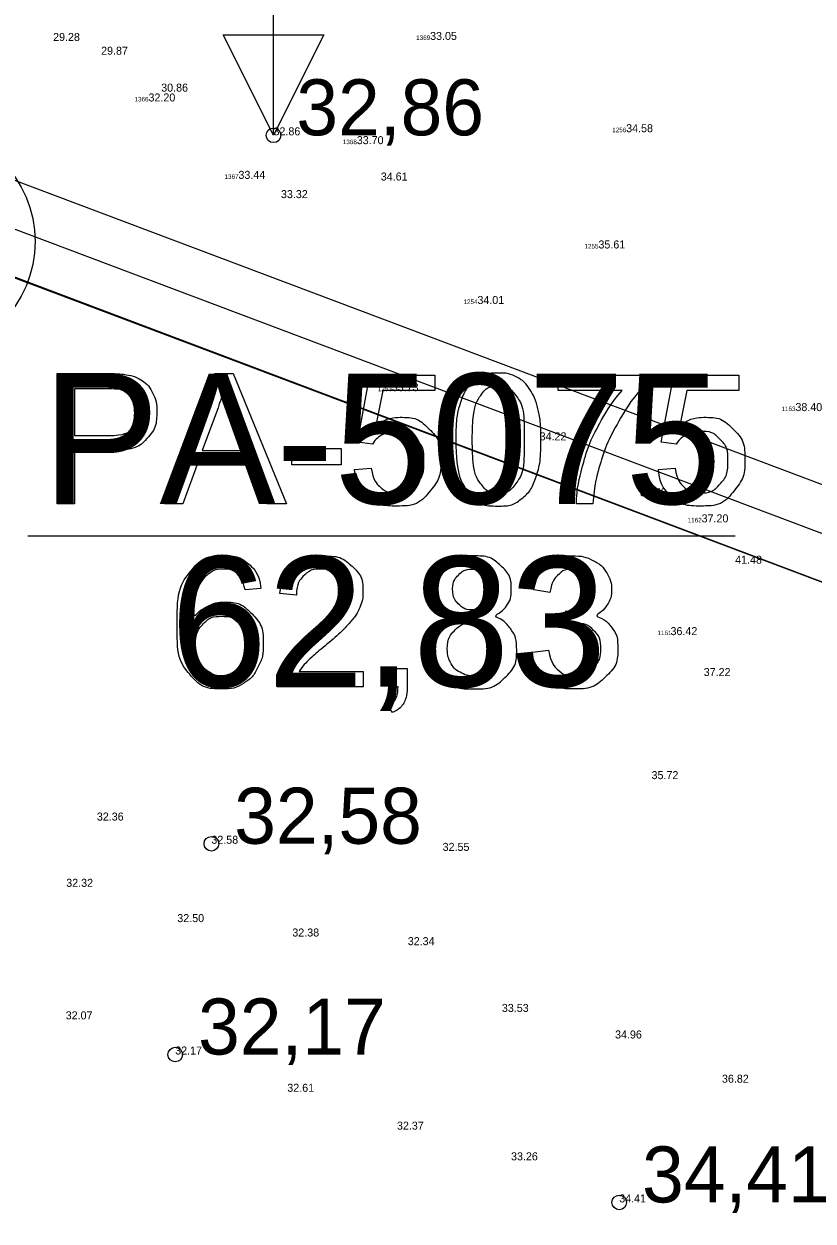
# Model space of a CAD drawing. Extents: x 700746 to 706058, y 6570320 to 6580460.
# Drawn here: x 703192.2 to 703226.7, y 6576956.8 to 6577009.2 of the extents above; entities that cross this region are included whole.
import ezdxf

# ---------------------------------------------------------------- set-up
doc = ezdxf.new("R2010")
doc.units = 0
for name, color, linetype in [('GEOLPUNKT', 7, 'Continuous'), ('illumineerimisjooned', 7, 'Continuous'), ('jääkpaksus', 7, 'Continuous'), ('KORGUS-EH2000', 7, 'Continuous'), ('maeeraldised_kehtivad', 7, 'Continuous'), ('MOOTKORG-EH2000', 7, 'Continuous'), ('MOOTNR', 7, 'Continuous'), ('Plokid', 7, 'Continuous'), ('VWX2_MV_PLOKK', 7, 'Continuous')]:
    doc.layers.add(name, color=color, linetype=linetype)

msp = doc.modelspace()

# ---------------------------------------------------------------- linework, layer by layer
at = {"layer": 'GEOLPUNKT'}
msp.add_line((703192.351, 6576986.805), (703223.262, 6576986.805), dxfattribs=at)
msp.add_line((703192.351, 6576986.805), (703223.262, 6576986.805), dxfattribs=at)
for points in [[(703193.634, 6576988.203), (703193.634, 6576993.903), (703195.785, 6576993.903)], [(703198.325, 6576988.203), (703200.516, 6576993.903), (703201.332, 6576993.903), (703203.66, 6576988.203), (703202.801, 6576988.203), (703202.141, 6576989.928), (703199.75, 6576989.928), (703199.125, 6576988.203), (703198.325, 6576988.203)], [(703207.41, 6576990.814), (703206.754, 6576990.901), (703207.306, 6576993.829), (703210.139, 6576993.829), (703210.139, 6576993.16), (703207.865, 6576993.16), (703207.558, 6576991.63)], [(703215.53, 6576993.156), (703215.53, 6576993.829), (703219.219, 6576993.829), (703219.219, 6576993.284)], [(703220.691, 6576990.814), (703220.035, 6576990.901), (703220.587, 6576993.829), (703223.42, 6576993.829), (703223.42, 6576993.16), (703221.146, 6576993.16), (703220.84, 6576991.63)], [(703195.848, 6576993.23), (703194.39, 6576993.23), (703194.39, 6576991.192)], [(703218.319, 6576993.156), (703215.53, 6576993.156)], [(703200.598, 6576992.214), (703199.968, 6576990.54)], [(703199.968, 6576990.54), (703201.904, 6576990.54), (703201.306, 6576992.123)], [(703194.39, 6576991.192), (703195.864, 6576991.192)], [(703203.896, 6576989.915), (703203.896, 6576990.619), (703206.05, 6576990.619), (703206.05, 6576989.915), (703203.896, 6576989.915)], [(703195.852, 6576990.519), (703194.39, 6576990.519), (703194.39, 6576988.203), (703193.634, 6576988.203)], [(703206.628, 6576989.698), (703207.362, 6576989.758)], [(703219.909, 6576989.698), (703220.644, 6576989.758)], [(703217.046, 6576988.203), (703216.325, 6576988.203)], [(703202.542, 6576984.504), (703201.847, 6576984.448)], [(703215.172, 6576984.322), (703214.472, 6576984.448)], [(703204.093, 6576984.204), (703203.372, 6576984.278)], [(703215.782, 6576982.905), (703215.86, 6576983.518)], [(703214.403, 6576981.715), (703215.102, 6576981.806)], [(703207.008, 6576980.876), (703207.008, 6576980.203), (703203.242, 6576980.203)], [(703204.215, 6576980.876), (703207.008, 6576980.876)], [(703208.138, 6576980.203), (703208.138, 6576980.998), (703208.933, 6576980.998), (703208.933, 6576980.203)], [(703208.534, 6576980.203), (703208.138, 6576980.203)], [(703208.286, 6576979.073), (703208.09, 6576979.373)]]:
    msp.add_lwpolyline(points, dxfattribs=at)
msp.add_circle((703187.671, 6576999.672), 5, dxfattribs=at)
for points in [[(703195.785, 6576993.903), (703196.353, 6576993.903), (703196.653, 6576993.849), (703197.073, 6576993.779), (703197.357, 6576993.582), (703197.641, 6576993.386), (703197.814, 6576993.032), (703197.987, 6576992.678), (703197.987, 6576992.254), (703197.987, 6576991.526), (703197.524, 6576991.022), (703197.061, 6576990.519), (703195.852, 6576990.519)], [(703211.055, 6576991.014), (703211.055, 6576992.024), (703211.263, 6576992.641), (703211.471, 6576993.259), (703211.881, 6576993.592), (703212.291, 6576993.925), (703212.913, 6576993.925), (703213.371, 6576993.925), (703213.718, 6576993.74), (703214.065, 6576993.556), (703214.289, 6576993.208), (703214.513, 6576992.86), (703214.642, 6576992.361), (703214.77, 6576991.861), (703214.77, 6576991.014), (703214.77, 6576990.012), (703214.564, 6576989.395), (703214.358, 6576988.777), (703213.948, 6576988.442), (703213.538, 6576988.107), (703212.913, 6576988.107), (703212.089, 6576988.107), (703211.619, 6576988.696), (703211.055, 6576989.409), (703211.055, 6576991.014)], [(703195.864, 6576991.192), (703196.595, 6576991.192), (703196.902, 6576991.464), (703197.209, 6576991.736), (703197.209, 6576992.23), (703197.209, 6576992.588), (703197.029, 6576992.843), (703196.848, 6576993.097), (703196.552, 6576993.179), (703196.362, 6576993.23), (703195.848, 6576993.23)], [(703211.776, 6576991.014), (703211.776, 6576989.608), (703212.104, 6576989.144), (703212.432, 6576988.681), (703212.913, 6576988.681), (703213.393, 6576988.681), (703213.721, 6576989.146), (703214.049, 6576989.612), (703214.049, 6576991.014), (703214.049, 6576992.421), (703213.722, 6576992.884), (703213.394, 6576993.347), (703212.905, 6576993.347), (703212.424, 6576993.347), (703212.136, 6576992.939), (703211.776, 6576992.418), (703211.776, 6576991.014)], [(703219.219, 6576993.284), (703218.675, 6576992.705), (703218.14, 6576991.745), (703217.606, 6576990.784), (703217.315, 6576989.77), (703217.105, 6576989.054), (703217.046, 6576988.203)], [(703201.306, 6576992.123), (703201.038, 6576992.844), (703200.904, 6576993.303), (703200.792, 6576992.756), (703200.598, 6576992.214)], [(703216.325, 6576988.203), (703216.337, 6576988.876), (703216.59, 6576989.828), (703216.842, 6576990.78), (703217.314, 6576991.665), (703217.787, 6576992.549), (703218.319, 6576993.156)], [(703207.558, 6576991.63), (703208.072, 6576991.987), (703208.635, 6576991.987), (703209.382, 6576991.987), (703209.895, 6576991.47), (703210.408, 6576990.952), (703210.408, 6576990.139), (703210.408, 6576989.364), (703209.957, 6576988.8), (703209.409, 6576988.107), (703208.46, 6576988.107), (703207.682, 6576988.107), (703207.19, 6576988.543), (703206.698, 6576988.978), (703206.628, 6576989.698)], [(703220.84, 6576991.63), (703221.353, 6576991.987), (703221.916, 6576991.987), (703222.663, 6576991.987), (703223.176, 6576991.47), (703223.689, 6576990.952), (703223.689, 6576990.139), (703223.689, 6576989.364), (703223.238, 6576988.8), (703222.69, 6576988.107), (703221.741, 6576988.107), (703220.963, 6576988.107), (703220.471, 6576988.543), (703219.979, 6576988.978), (703219.909, 6576989.698)], [(703207.362, 6576989.758), (703207.444, 6576989.222), (703207.741, 6576988.951), (703208.037, 6576988.681), (703208.459, 6576988.681), (703208.968, 6576988.681), (703209.317, 6576989.063), (703209.665, 6576989.445), (703209.665, 6576990.076), (703209.665, 6576990.676), (703209.33, 6576991.023), (703208.996, 6576991.37), (703208.448, 6576991.37), (703208.108, 6576991.37), (703207.837, 6576991.215), (703207.566, 6576991.061), (703207.41, 6576990.814)], [(703220.644, 6576989.758), (703220.725, 6576989.222), (703221.022, 6576988.951), (703221.318, 6576988.681), (703221.741, 6576988.681), (703222.249, 6576988.681), (703222.598, 6576989.063), (703222.946, 6576989.445), (703222.946, 6576990.076), (703222.946, 6576990.676), (703222.612, 6576991.023), (703222.277, 6576991.37), (703221.729, 6576991.37), (703221.389, 6576991.37), (703221.118, 6576991.215), (703220.847, 6576991.061), (703220.691, 6576990.814)], [(703201.847, 6576984.448), (703201.754, 6576984.862), (703201.582, 6576985.05), (703201.297, 6576985.351), (703200.88, 6576985.351), (703200.545, 6576985.351), (703200.29, 6576985.165), (703199.96, 6576984.923), (703199.769, 6576984.46), (703199.578, 6576983.997), (703199.571, 6576983.142), (703199.824, 6576983.527), (703200.19, 6576983.714), (703200.556, 6576983.9), (703200.956, 6576983.9), (703201.657, 6576983.9), (703202.15, 6576983.385), (703202.642, 6576982.87), (703202.642, 6576982.054), (703202.642, 6576981.518), (703202.411, 6576981.058), (703202.179, 6576980.597), (703201.774, 6576980.352), (703201.37, 6576980.107), (703200.856, 6576980.107), (703199.981, 6576980.107), (703199.428, 6576980.751), (703198.875, 6576981.394), (703198.875, 6576982.87), (703198.875, 6576984.522), (703199.487, 6576985.272), (703200.02, 6576985.925), (703200.923, 6576985.925), (703201.596, 6576985.925), (703202.026, 6576985.547), (703202.457, 6576985.17), (703202.542, 6576984.504)], [(703203.372, 6576984.278), (703203.446, 6576985.082), (703203.928, 6576985.503), (703204.41, 6576985.925), (703205.223, 6576985.925), (703206.043, 6576985.925), (703206.521, 6576985.47), (703207, 6576985.015), (703207, 6576984.343), (703207, 6576984.001), (703206.86, 6576983.671), (703206.72, 6576983.341), (703206.396, 6576982.975), (703206.072, 6576982.61), (703205.319, 6576981.973), (703204.689, 6576981.444), (703204.51, 6576981.255), (703204.331, 6576981.067), (703204.215, 6576980.876)], [(703211.053, 6576983.296), (703210.615, 6576983.456), (703210.404, 6576983.751), (703210.193, 6576984.046), (703210.193, 6576984.457), (703210.193, 6576985.078), (703210.639, 6576985.502), (703211.086, 6576985.925), (703211.828, 6576985.925), (703212.573, 6576985.925), (703213.027, 6576985.492), (703213.482, 6576985.059), (703213.482, 6576984.438), (703213.482, 6576984.042), (703213.273, 6576983.749), (703213.065, 6576983.456), (703212.641, 6576983.296), (703213.167, 6576983.125), (703213.442, 6576982.744), (703213.716, 6576982.363), (703213.716, 6576981.834), (703213.716, 6576981.103), (703213.2, 6576980.605), (703212.683, 6576980.107), (703211.839, 6576980.107), (703210.996, 6576980.107), (703210.479, 6576980.607), (703209.963, 6576981.107), (703209.963, 6576981.854), (703209.963, 6576982.41), (703210.246, 6576982.785), (703210.529, 6576983.16), (703211.053, 6576983.296)], [(703214.472, 6576984.448), (703214.601, 6576985.151), (703215.056, 6576985.538), (703215.511, 6576985.925), (703216.188, 6576985.925), (703216.655, 6576985.925), (703217.048, 6576985.725), (703217.44, 6576985.525), (703217.649, 6576985.179), (703217.857, 6576984.834), (703217.857, 6576984.446), (703217.857, 6576984.077), (703217.658, 6576983.774), (703217.46, 6576983.471), (703217.071, 6576983.293), (703217.577, 6576983.176), (703217.856, 6576982.809), (703218.135, 6576982.442), (703218.135, 6576981.891), (703218.135, 6576981.145), (703217.59, 6576980.626), (703217.046, 6576980.107), (703216.214, 6576980.107), (703215.464, 6576980.107), (703214.968, 6576980.555), (703214.473, 6576981.003), (703214.403, 6576981.715)], [(703203.242, 6576980.203), (703203.234, 6576980.456), (703203.323, 6576980.69), (703203.467, 6576981.075), (703203.785, 6576981.448), (703204.102, 6576981.821), (703204.7, 6576982.31), (703205.628, 6576983.073), (703205.953, 6576983.518), (703206.279, 6576983.963), (703206.279, 6576984.36), (703206.279, 6576984.776), (703205.982, 6576985.061), (703205.685, 6576985.347), (703205.207, 6576985.347), (703204.703, 6576985.347), (703204.4, 6576985.044), (703204.097, 6576984.741), (703204.093, 6576984.204)], [(703210.914, 6576984.482), (703210.914, 6576984.078), (703211.172, 6576983.822), (703211.43, 6576983.566), (703211.845, 6576983.566), (703212.249, 6576983.566), (703212.505, 6576983.82), (703212.761, 6576984.074), (703212.761, 6576984.443), (703212.761, 6576984.827), (703212.497, 6576985.089), (703212.233, 6576985.351), (703211.837, 6576985.351), (703211.437, 6576985.351), (703211.176, 6576985.095), (703210.914, 6576984.839), (703210.914, 6576984.482)], [(703215.86, 6576983.518), (703215.93, 6576983.51), (703215.973, 6576983.51), (703216.42, 6576983.51), (703216.778, 6576983.743), (703217.135, 6576983.976), (703217.135, 6576984.462), (703217.135, 6576984.846), (703216.875, 6576985.099), (703216.614, 6576985.351), (703216.202, 6576985.351), (703215.794, 6576985.351), (703215.522, 6576985.094), (703215.25, 6576984.836), (703215.172, 6576984.322)], [(703199.679, 6576982.05), (703199.679, 6576981.688), (703199.833, 6576981.358), (703199.986, 6576981.027), (703200.261, 6576980.854), (703200.536, 6576980.681), (703200.841, 6576980.681), (703201.286, 6576980.681), (703201.603, 6576981.039), (703201.921, 6576981.397), (703201.921, 6576982.011), (703201.921, 6576982.603), (703201.607, 6576982.943), (703201.294, 6576983.283), (703200.814, 6576983.283), (703200.34, 6576983.283), (703200.009, 6576982.943), (703199.679, 6576982.603), (703199.679, 6576982.05)], [(703210.684, 6576981.848), (703210.684, 6576981.549), (703210.824, 6576981.268), (703210.964, 6576980.988), (703211.244, 6576980.835), (703211.524, 6576980.681), (703211.845, 6576980.681), (703212.347, 6576980.681), (703212.671, 6576981.004), (703212.995, 6576981.327), (703212.995, 6576981.825), (703212.995, 6576982.331), (703212.661, 6576982.661), (703212.328, 6576982.992), (703211.822, 6576982.992), (703211.328, 6576982.992), (703211.006, 6576982.665), (703210.684, 6576982.338), (703210.684, 6576981.848)], [(703215.102, 6576981.806), (703215.223, 6576981.211), (703215.511, 6576980.948), (703215.8, 6576980.685), (703216.218, 6576980.685), (703216.714, 6576980.685), (703217.053, 6576981.027), (703217.392, 6576981.37), (703217.392, 6576981.875), (703217.392, 6576982.357), (703217.077, 6576982.67), (703216.762, 6576982.983), (703216.276, 6576982.983), (703216.078, 6576982.983), (703215.782, 6576982.905)], [(703208.09, 6576979.373), (703208.312, 6576979.471), (703208.417, 6576979.66), (703208.522, 6576979.849), (703208.534, 6576980.203)], [(703208.933, 6576980.203), (703208.933, 6576979.763), (703208.778, 6576979.492), (703208.623, 6576979.221), (703208.286, 6576979.073)]]:
    msp.add_open_spline(points, degree=3, dxfattribs=at)
at = {"layer": 'illumineerimisjooned'}
msp.add_lwpolyline([(703290.041, 6576963.147), (703188.508, 6577001.438), (703016.934, 6577112.515), (702852.033, 6577230.395), (702862.776, 6577281.723), (703065.707, 6577215.464), (703087.928, 6577208.218), (703167.838, 6577148.861), (703229.081, 6577103.342), (703273.601, 6577070.555), (703290.041, 6576963.147)], dxfattribs=at)
at = {"layer": 'jääkpaksus'}
msp.add_lwpolyline([(703203.089, 6577004.321), (703203.089, 6577010.921), (703225.089, 6577010.921)], dxfattribs=at)
msp.add_lwpolyline([(703203.089, 6577004.321), (703200.889, 6577008.721), (703205.289, 6577008.721)], close=True, dxfattribs=at)
at = {"layer": 'KORGUS-EH2000'}
for centre in [(703203.089, 6577004.321), (703200.373, 6576973.335), (703198.794, 6576964.117), (703218.197, 6576957.648)]:
    msp.add_circle(centre, 0.32, dxfattribs=at)
at = {"layer": 'maeeraldised_kehtivad'}
msp.add_lwpolyline([(702849.808, 6577229.527), (702861.724, 6577286.461), (703066.949, 6577219.266), (703089.789, 6577211.819), (703170.224, 6577152.072), (703231.46, 6577106.558), (703277.305, 6577072.795), (703294.683, 6576959.259), (703187.602, 6576999.642), (703015.809, 6577110.861)], close=True, dxfattribs=at)
at = {"layer": 'Plokid'}
msp.add_lwpolyline([(703287.547, 6576966.226), (703189.415, 6577003.234), (703018.06, 6577114.169), (702854.258, 6577231.263), (702863.9, 6577277.331), (703064.465, 6577211.662), (703086.067, 6577204.618), (703165.453, 6577145.65), (703226.702, 6577100.127), (703272.178, 6577066.636)], close=True, dxfattribs=at)
at = {"layer": 'VWX2_MV_PLOKK'}
for points in [[(702849.88, 6577229.56), (702861.72, 6577286.46), (703066.96, 6577219.29), (703089.79, 6577211.82), (703170.22, 6577152.07), (703231.53, 6577106.55), (703277.36, 6577072.83), (703294.74, 6576959.21), (703187.67, 6576999.67), (703015.74, 6577110.88)], [(702849.88, 6577229.56), (702861.72, 6577286.46), (703066.96, 6577219.29), (703089.79, 6577211.82), (703170.22, 6577152.07), (703231.53, 6577106.55), (703277.36, 6577072.83), (703294.74, 6576959.21), (703187.67, 6576999.67), (703015.74, 6577110.88)], [(703187.67, 6576999.67), (703294.74, 6576959.21), (703340.88, 6576657.54), (703190.39, 6576656.32)], [(703187.67, 6576999.67), (703294.74, 6576959.21), (703340.88, 6576657.54), (703190.39, 6576656.32)]]:
    msp.add_lwpolyline(points, close=True, dxfattribs=at)

# ---------------------------------------------------------------- texts
at = {"layer": 'GEOLPUNKT'}
for s, p in [('PA-5075', (703193.021, 6576988.203)), ('62,83', (703198.576, 6576980.203))]:
    msp.add_text(s, height=5.7, dxfattribs=at).set_placement(p)
at = {"layer": 'KORGUS-EH2000'}
for s, p in [('32,86', (703204.089, 6577004.321)), ('32,58', (703201.373, 6576973.335)), ('32,17', (703199.794, 6576964.117)), ('34,41', (703219.197, 6576957.648))]:
    msp.add_text(s, height=2.45, dxfattribs=at).set_placement(p)
at = {"layer": 'MOOTKORG-EH2000'}
for s, p in [('29.28', (703193.458, 6577008.447)), ('33.05', (703209.933, 6577008.493)), ('29.87', (703195.555, 6577007.846)), ('30.86', (703198.181, 6577006.233)), ('32.20', (703197.626, 6577005.803)), ('34.58', (703218.501, 6577004.457)), ('32.86', (703203.089, 6577004.321)), ('33.70', (703206.727, 6577003.935)), ('33.44', (703201.556, 6577002.417)), ('34.61', (703207.777, 6577002.345)), ('33.32', (703203.415, 6577001.575)), ('35.61', (703217.288, 6576999.372)), ('34.01', (703212, 6576996.943)), ('33.73', (703208.258, 6576993.131)), ('38.40', (703225.897, 6576992.26)), ('34.22', (703214.719, 6576990.979)), ('35.79', (703219.099, 6576988.532)), ('37.20', (703221.796, 6576987.392)), ('41.48', (703223.263, 6576985.584)), ('36.42', (703220.439, 6576982.461)), ('37.22', (703221.89, 6576980.67)), ('35.72', (703219.61, 6576976.162)), ('32.36', (703195.369, 6576974.35)), ('32.58', (703200.373, 6576973.335)), ('32.55', (703210.48, 6576973.024)), ('32.32', (703194.031, 6576971.452)), ('32.50', (703198.885, 6576969.908)), ('32.38', (703203.912, 6576969.279)), ('32.34', (703208.956, 6576968.9)), ('32.07', (703194.008, 6576965.655)), ('33.53', (703213.069, 6576965.979)), ('34.96', (703218.015, 6576964.818)), ('32.17', (703198.794, 6576964.117)), ('36.82', (703222.687, 6576962.884)), ('32.61', (703203.693, 6576962.487)), ('32.37', (703208.484, 6576960.831)), ('33.26', (703213.469, 6576959.489)), ('34.41', (703218.197, 6576957.648))]:
    msp.add_text(s, height=0.35, dxfattribs=at).set_placement(p)
at = {"layer": 'MOOTNR'}
for s, p in [('1369', (703209.324, 6577008.493)), ('1366', (703197.017, 6577005.803)), ('1256', (703217.892, 6577004.457)), ('1368', (703206.118, 6577003.935)), ('1367', (703200.947, 6577002.417)), ('1255', (703216.678, 6576999.372)), ('1254', (703211.392, 6576996.943)), ('1253', (703207.649, 6576993.131)), ('1163', (703225.288, 6576992.26)), ('1162', (703221.189, 6576987.392)), ('1161', (703219.869, 6576982.461))]:
    msp.add_text(s, height=0.2, dxfattribs=at).set_placement(p)

doc.saveas('drawing.dxf')
